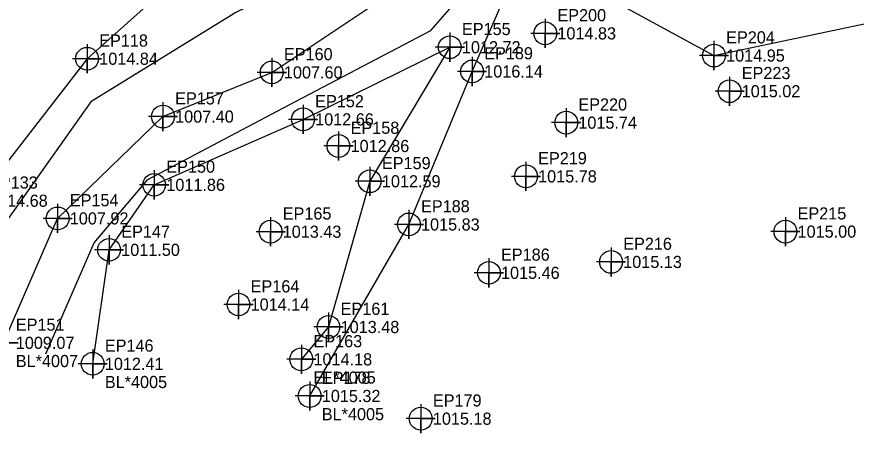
# Model space of a CAD drawing. Extents: x 1382561 to 1383039, y 884068 to 884307.
# Drawn here: x 1382691.1 to 1382864, y 884068.3 to 884154.1 of the extents above; entities that cross this region are included whole.
import ezdxf

# ---------------------------------------------------------------- set-up
doc = ezdxf.new("R2010")
doc.units = 0
for name, color, linetype in [('Exist DTM Breakline', 7, 'Continuous'), ('Exist DTM Breakline Cogo Comment', 7, 'Continuous'), ('Exist DTM Breakline Cogo Elevation', 7, 'Continuous'), ('Exist DTM Breakline Cogo Number', 7, 'Continuous'), ('Exist DTM Breakline Cogo Point CELL', 7, 'Continuous'), ('Exist DTM Breakline Underwater', 7, 'Continuous'), ('Exist DTM Breakline Underwater Cogo Comment', 7, 'Continuous'), ('Exist DTM Breakline Underwater Cogo Elevation', 7, 'Continuous'), ('Exist DTM Breakline Underwater Cogo Number', 7, 'Continuous'), ('Exist DTM Breakline Underwater Cogo Point CELL', 7, 'Continuous'), ('Exist DTM Regular Point CELL', 7, 'Continuous'), ('Exist DTM Regular Point Cogo Elevation', 7, 'Continuous'), ('Exist DTM Regular Point Cogo Number', 7, 'Continuous'), ('Exist Hydro Stream or Body of Water', 7, 'Continuous')]:
    doc.layers.add(name, color=color, linetype=linetype)

msp = doc.modelspace()

# ---------------------------------------------------------------- linework, layer by layer
at = {"layer": 'Exist DTM Breakline'}
for points in [[(1382751.4287, 884075.9856), (1382771.8716, 884111.3375), (1382784.8942, 884142.8663), (1382794.19, 884164.1279), (1382801.7626, 884181.793), (1382802.1903, 884175.7622), (1382803.9822, 884162.9447), (1382834.7331, 884146.1448), (1382885.2227, 884156.817), (1382912.2708, 884159.0791), (1382962.484, 884168.5252), (1383014.0488, 884181.852)], [(1382765.9243, 884175.6081), (1382754.8134, 884167.9678), (1382731.7194, 884159.5309), (1382722.2333, 884160.3495), (1382705.5702, 884145.487), (1382682.8713, 884116.2267), (1382674.3334, 884104.2092), (1382674.6208, 884111.7647), (1382664.0032, 884106.0759), (1382669.8487, 884092.884)], [(1382706.7251, 884082.6164), (1382710.1022, 884106.0996), (1382719.3913, 884119.4989), (1382750.0599, 884132.9899), (1382780.2966, 884147.8621), (1382763.8127, 884120.2288), (1382755.3088, 884090.2031), (1382749.7127, 884083.538)]]:
    msp.add_lwpolyline(points, dxfattribs=at)
at = {"layer": 'Exist DTM Breakline Cogo Point CELL'}
for points in [[(1382780.2966, 884150.8621), (1382780.2966, 884144.8621), (1382780.2966, 884147.8621), (1382783.2966, 884147.8621), (1382777.2966, 884147.8621)], [(1382705.5702, 884148.487), (1382705.5702, 884142.487), (1382705.5702, 884145.487), (1382708.5702, 884145.487), (1382702.5702, 884145.487)], [(1382834.7331, 884149.1448), (1382834.7331, 884143.1448), (1382834.7331, 884146.1448), (1382837.7331, 884146.1448), (1382831.7331, 884146.1448)], [(1382784.8942, 884145.8663), (1382784.8942, 884139.8663), (1382784.8942, 884142.8663), (1382787.8942, 884142.8663), (1382781.8942, 884142.8663)], [(1382750.0599, 884135.9899), (1382750.0599, 884129.9899), (1382750.0599, 884132.9899), (1382753.0599, 884132.9899), (1382747.0599, 884132.9899)], [(1382719.3913, 884122.4989), (1382719.3913, 884116.4989), (1382719.3913, 884119.4989), (1382722.3913, 884119.4989), (1382716.3913, 884119.4989)], [(1382763.8127, 884123.2288), (1382763.8127, 884117.2288), (1382763.8127, 884120.2288), (1382766.8127, 884120.2288), (1382760.8127, 884120.2288)], [(1382771.8716, 884114.3375), (1382771.8716, 884108.3375), (1382771.8716, 884111.3375), (1382774.8716, 884111.3375), (1382768.8716, 884111.3375)], [(1382710.1022, 884109.0996), (1382710.1022, 884103.0996), (1382710.1022, 884106.0996), (1382713.1022, 884106.0996), (1382707.1022, 884106.0996)], [(1382755.3088, 884093.2031), (1382755.3088, 884087.2031), (1382755.3088, 884090.2031), (1382758.3088, 884090.2031), (1382752.3088, 884090.2031)], [(1382749.7127, 884086.538), (1382749.7127, 884080.538), (1382749.7127, 884083.538), (1382752.7127, 884083.538), (1382746.7127, 884083.538)], [(1382706.7251, 884085.6164), (1382706.7251, 884079.6164), (1382706.7251, 884082.6164), (1382709.7251, 884082.6164), (1382703.7251, 884082.6164)], [(1382751.4287, 884078.9856), (1382751.4287, 884072.9856), (1382751.4287, 884075.9856), (1382754.4287, 884075.9856), (1382748.4287, 884075.9856)]]:
    msp.add_lwpolyline(points, dxfattribs=at)
for centre in [(1382780.2966, 884147.8621), (1382834.7331, 884146.1448), (1382705.5702, 884145.487), (1382784.8942, 884142.8663), (1382750.0599, 884132.9899), (1382763.8127, 884120.2288), (1382719.3913, 884119.4989), (1382771.8716, 884111.3375), (1382710.1022, 884106.0996), (1382755.3088, 884090.2031), (1382706.7251, 884082.6164), (1382749.7127, 884083.538), (1382751.4287, 884075.9856)]:
    msp.add_circle(centre, 2.344, dxfattribs=at)
at = {"layer": 'Exist DTM Breakline Underwater'}
msp.add_lwpolyline([(1382688.3783, 884086.9383), (1382699.504, 884112.5821), (1382721.2073, 884133.5617), (1382743.6214, 884142.6712), (1382769.5658, 884160.0329), (1382785.1067, 884174.8132), (1382789.3291, 884181.9565), (1382809.982, 884219.9732), (1382816.0046, 884242.1273), (1382837.3981, 884258.7844), (1382845.6113, 884276.5289)], dxfattribs=at)
at = {"layer": 'Exist DTM Breakline Underwater Cogo Point CELL'}
for points in [[(1382743.6214, 884145.6712), (1382743.6214, 884139.6712), (1382743.6214, 884142.6712), (1382746.6214, 884142.6712), (1382740.6214, 884142.6712)], [(1382721.2073, 884136.5617), (1382721.2073, 884130.5617), (1382721.2073, 884133.5617), (1382724.2073, 884133.5617), (1382718.2073, 884133.5617)], [(1382699.504, 884115.5821), (1382699.504, 884109.5821), (1382699.504, 884112.5821), (1382702.504, 884112.5821), (1382696.504, 884112.5821)], [(1382688.3783, 884089.9383), (1382688.3783, 884083.9383), (1382688.3783, 884086.9383), (1382691.3783, 884086.9383), (1382685.3783, 884086.9383)]]:
    msp.add_lwpolyline(points, dxfattribs=at)
for centre in [(1382743.6214, 884142.6712), (1382721.2073, 884133.5617), (1382699.504, 884112.5821)]:
    msp.add_circle(centre, 2.344, dxfattribs=at)
at = {"layer": 'Exist DTM Regular Point CELL'}
for points in [[(1382799.9651, 884153.7126), (1382799.9651, 884147.7126), (1382799.9651, 884150.7126), (1382802.9651, 884150.7126), (1382796.9651, 884150.7126)], [(1382837.9404, 884141.7898), (1382837.9404, 884135.7898), (1382837.9404, 884138.7898), (1382840.9404, 884138.7898), (1382834.9404, 884138.7898)], [(1382804.2849, 884135.3149), (1382804.2849, 884129.3149), (1382804.2849, 884132.3149), (1382807.2849, 884132.3149), (1382801.2849, 884132.3149)], [(1382757.3618, 884130.5056), (1382757.3618, 884124.5056), (1382757.3618, 884127.5056), (1382760.3618, 884127.5056), (1382754.3618, 884127.5056)], [(1382795.9952, 884124.2452), (1382795.9952, 884118.2452), (1382795.9952, 884121.2452), (1382798.9952, 884121.2452), (1382792.9952, 884121.2452)], [(1382743.3726, 884112.84), (1382743.3726, 884106.84), (1382743.3726, 884109.84), (1382746.3726, 884109.84), (1382740.3726, 884109.84)], [(1382849.449, 884112.8555), (1382849.449, 884106.8555), (1382849.449, 884109.8555), (1382852.449, 884109.8555), (1382846.449, 884109.8555)], [(1382813.5284, 884106.6089), (1382813.5284, 884100.6089), (1382813.5284, 884103.6089), (1382816.5284, 884103.6089), (1382810.5284, 884103.6089)], [(1382788.348, 884104.3675), (1382788.348, 884098.3675), (1382788.348, 884101.3675), (1382791.348, 884101.3675), (1382785.348, 884101.3675)], [(1382736.7652, 884097.8341), (1382736.7652, 884091.8341), (1382736.7652, 884094.8341), (1382739.7652, 884094.8341), (1382733.7652, 884094.8341)], [(1382774.3141, 884074.3115), (1382774.3141, 884068.3115), (1382774.3141, 884071.3115), (1382777.3141, 884071.3115), (1382771.3141, 884071.3115)]]:
    msp.add_lwpolyline(points, dxfattribs=at)
for centre in [(1382799.9651, 884150.7126), (1382837.9404, 884138.7898), (1382804.2849, 884132.3149), (1382757.3618, 884127.5056), (1382795.9952, 884121.2452), (1382743.3726, 884109.84), (1382849.449, 884109.8555), (1382813.5284, 884103.6089), (1382788.348, 884101.3675), (1382736.7652, 884094.8341), (1382774.3141, 884071.3115)]:
    msp.add_circle(centre, 2.344, dxfattribs=at)
at = {"layer": 'Exist Hydro Stream or Body of Water'}
for points in [[(1382815.7469, 884285.0295), (1382796.5538, 884263.5381), (1382784.2894, 884233.9786), (1382781.1386, 884206.3096), (1382772.3397, 884180.9543), (1382766.7799, 884172.9781), (1382757.421, 884165.3571), (1382736.1951, 884155.0402), (1382706.3401, 884136.6072), (1382689.3837, 884112.6314), (1382676.096, 884092.4493)], [(1382697.0874, 884084.7019), (1382707.0296, 884107.5273), (1382718.101, 884120.6229), (1382747.1797, 884135.9958), (1382776.4132, 884151.3238), (1382791.7634, 884168.9711), (1382798.6691, 884182.5745), (1382820.5432, 884217.5751), (1382820.037, 884238.4145), (1382839.3094, 884257.7694), (1382850.1603, 884274.5827)]]:
    msp.add_lwpolyline(points, dxfattribs=at)

# ---------------------------------------------------------------- texts
at = {"layer": 'Exist DTM Breakline Cogo Comment'}
for s, p in [('EL*4005', (1382752.2127, 884078.538)), ('BL*4005', (1382709.2251, 884077.6164)), ('BL*4005', (1382753.9287, 884070.9856))]:
    msp.add_text(s, height=2.5, dxfattribs=at).set_placement(p)
at = {"layer": 'Exist DTM Breakline Cogo Elevation'}
for s, p in [('1012.72', (1382782.7966, 884146.6121)), ('1014.84', (1382708.0702, 884144.237)), ('1014.95', (1382837.2331, 884144.8948)), ('1016.14', (1382787.3942, 884141.6163)), ('1012.66', (1382752.5599, 884131.7399)), ('1011.86', (1382721.8913, 884118.2489)), ('1012.59', (1382766.3127, 884118.9788)), ('1014.68', (1382685.3713, 884114.9767)), ('1015.83', (1382774.3716, 884110.0875)), ('1011.50', (1382712.6022, 884104.8496)), ('1013.48', (1382757.8088, 884088.9531)), ('1014.18', (1382752.2127, 884082.288)), ('1012.41', (1382709.2251, 884081.3664)), ('1015.32', (1382753.9287, 884074.7356))]:
    msp.add_text(s, height=2.5, dxfattribs=at).set_placement(p)
at = {"layer": 'Exist DTM Breakline Cogo Number'}
for s, p in [('EP155', (1382782.7966, 884150.3621)), ('EP118', (1382708.0702, 884147.987)), ('EP204', (1382837.2331, 884148.6448)), ('EP189', (1382787.3942, 884145.3663)), ('EP152', (1382752.5599, 884135.4899)), ('EP150', (1382721.8913, 884121.9989)), ('EP159', (1382766.3127, 884122.7288)), ('EP133', (1382685.3713, 884118.7267)), ('EP188', (1382774.3716, 884113.8375)), ('EP147', (1382712.6022, 884108.5996)), ('EP161', (1382757.8088, 884092.7031)), ('EP163', (1382752.2127, 884086.038)), ('EP146', (1382709.2251, 884085.1164)), ('EP178', (1382753.9287, 884078.4856))]:
    msp.add_text(s, height=2.5, dxfattribs=at).set_placement(p)
at = {"layer": 'Exist DTM Breakline Underwater Cogo Comment'}
msp.add_text('BL*4007', height=2.5, dxfattribs=at).set_placement((1382690.8783, 884081.9383))
at = {"layer": 'Exist DTM Breakline Underwater Cogo Elevation'}
for s, p in [('1007.60', (1382746.1214, 884141.4212)), ('1007.40', (1382723.7073, 884132.3117)), ('1007.92', (1382702.004, 884111.3321)), ('1009.07', (1382690.8783, 884085.6883))]:
    msp.add_text(s, height=2.5, dxfattribs=at).set_placement(p)
at = {"layer": 'Exist DTM Breakline Underwater Cogo Number'}
for s, p in [('EP160', (1382746.1214, 884145.1712)), ('EP157', (1382723.7073, 884136.0617)), ('EP154', (1382702.004, 884115.0821)), ('EP151', (1382690.8783, 884089.4383))]:
    msp.add_text(s, height=2.5, dxfattribs=at).set_placement(p)
at = {"layer": 'Exist DTM Regular Point Cogo Elevation'}
for s, p in [('1014.83', (1382802.4651, 884149.4626)), ('1015.02', (1382840.4404, 884137.5398)), ('1015.74', (1382806.7849, 884131.0649)), ('1012.86', (1382759.8618, 884126.2556)), ('1015.78', (1382798.4952, 884119.9952)), ('1013.43', (1382745.8726, 884108.59)), ('1015.00', (1382851.949, 884108.6055)), ('1015.13', (1382816.0284, 884102.3589)), ('1015.46', (1382790.848, 884100.1175)), ('1014.14', (1382739.2652, 884093.5841)), ('1015.18', (1382776.8141, 884070.0615))]:
    msp.add_text(s, height=2.5, dxfattribs=at).set_placement(p)
at = {"layer": 'Exist DTM Regular Point Cogo Number'}
for s, p in [('EP200', (1382802.4651, 884153.2126)), ('EP223', (1382840.4404, 884141.2898)), ('EP220', (1382806.7849, 884134.8149)), ('EP158', (1382759.8618, 884130.0056)), ('EP219', (1382798.4952, 884123.7452)), ('EP165', (1382745.8726, 884112.34)), ('EP215', (1382851.949, 884112.3555)), ('EP216', (1382816.0284, 884106.1089)), ('EP186', (1382790.848, 884103.8675)), ('EP164', (1382739.2652, 884097.3341)), ('EP179', (1382776.8141, 884073.8115))]:
    msp.add_text(s, height=2.5, dxfattribs=at).set_placement(p)

doc.saveas('drawing.dxf')
